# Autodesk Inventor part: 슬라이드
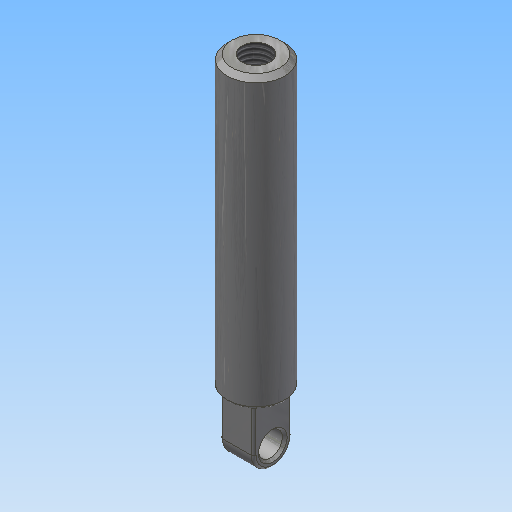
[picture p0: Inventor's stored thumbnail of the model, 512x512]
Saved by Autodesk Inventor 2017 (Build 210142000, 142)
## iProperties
Created: 2016-02
Part Number: 슬라이드
Material: 강철, 연강
Document SubType Name: Modeling
Designer: test
Density: 1 g/cm^3
Appearance: 강철
Author: test
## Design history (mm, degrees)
sketch "스케치2"
  geometry: C1 r 6 at (0, 0); 1 further point
  constraints: 1 centre point, 1 coincident
  dimensions: "d0" = 12 diameter of C1
extrude "돌출1" new body sketch "스케치2" distance "d1" = 60; taper "d2" = 0 deg
hole "구멍1" diameter "d5" = 5.917; stored, may be unused: countersink angle "d9" = 90 deg, drill point angle "d11" = 118 deg; dims "d3" = 10, "d4" = 10, "d6" = 10, "d7" = 4, "d8" = 2, "d10" = 12
chamfer "모따기1" distance "d12" = 1; stored, may be unused: second distance "d13" = 2, angle "d14" = 45 deg
sketch "스케치3"
  geometry: L1 (0, 6)-(0, -6) reference; L2 (0, 4)-(-9, 4); L3 (-9, -4)-(0, -4); L4 (0, -4)-(0, 4); C1 r 2.5 at (-9, 0); A1 r 4 centre (-9, 0) between (-9, 4) and (-9, -4); 2 further points
  constraints: 6 end point, 2 centre point, 2 point on circle, 2 tangent, 1 coincident, 1 horizontal, 1 horizontal alignment, 1 midpoint, 1 parallel, 1 point on line, 1 vertical
  dimensions: "d15" = 13 dimension on A1 L1; "d16" = 8 distance between parallel lines of L3 L2; "d17" = 5 diameter of C1
extrude "돌출2" join sketch "스케치3" stored distance "d18" = 7; taper "d19" = 0 deg
chamfer "모따기2" distance "d20" = 0.5; stored, may be unused: second distance "d21" = 2, angle "d22" = 45 deg
fillet "모깎기1" dims "d23" = 0.5
fillet "모깎기2" dims "d24" = 0.5
fillet "모깎기3" dims "d25" = 0.5
node "솔리드1"
